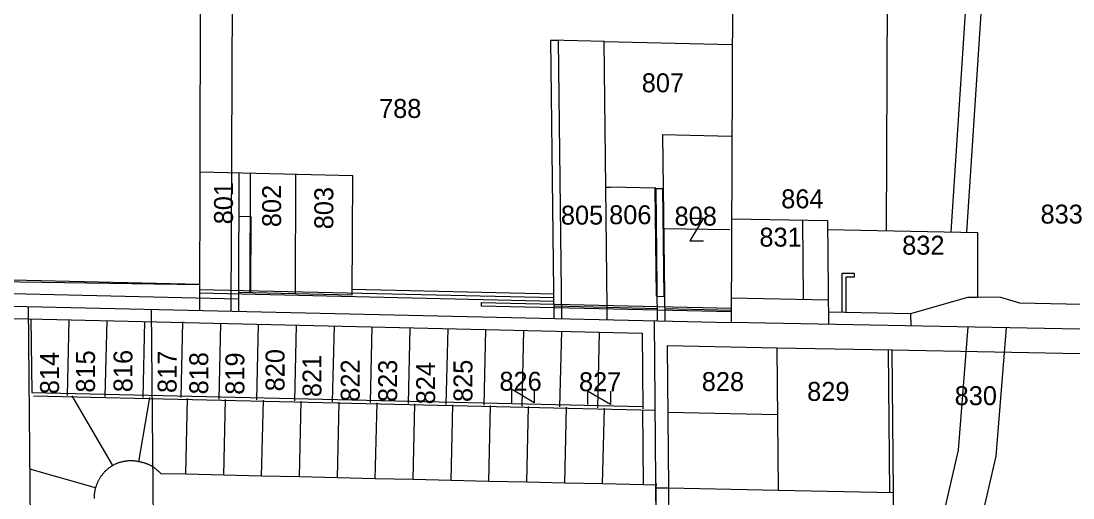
# Model space of a CAD drawing. Extents: x 582596 to 627039, y 145946 to 197316.
# Drawn here: x 613327 to 616103, y 164266 to 165524 of the extents above; entities that cross this region are included whole.
import ezdxf

# ---------------------------------------------------------------- set-up
doc = ezdxf.new("R2010")
doc.units = 0
for name, color, linetype in [('Defpoints 2', 7, 'Continuous'), ('E_RW_Easement', 7, 'Continuous'), ('E_RW_EasementUtility', 7, 'Continuous'), ('E_RW_Existing', 7, 'Continuous'), ('E_RW_SixteenthLine', 7, 'Continuous'), ('P_RW_MinorLotLine', 7, 'Continuous'), ('P_RW_PropertyConnector', 7, 'Continuous'), ('P_RW_PropertyLine', 7, 'Continuous'), ('P_RW_SectionLine', 7, 'Continuous')]:
    doc.layers.add(name, color=color, linetype=linetype)

msp = doc.modelspace()

# ---------------------------------------------------------------- linework, layer by layer
at = {"layer": 'E_RW_Easement'}
for p, q in [((615003.8, 164798), (615000.3, 165082.3)), ((615000.3, 165082.3), (615020.3, 165081.8)), ((615020.3, 165081.8), (615023.8, 164797)), ((613934.1, 165007.7), (613901.8, 165008.4)), ((613933.2, 164807.6), (613934.1, 165007.7)), ((615389.6, 164998.9), (615391.2, 164789.9)), ((613352.7, 164738), (613355.6, 164543.9)), ((613355.6, 164543.9), (614967.8, 164506.7))]:
    msp.add_line(p, q, dxfattribs=at)
at = {"layer": 'E_RW_EasementUtility'}
for p, q in [((612654.1, 164845.1), (613797.7, 164828.8)), ((613797.7, 164828.8), (612655.2, 164855.1)), ((615494.2, 164756), (615494.2, 164858.6)), ((615494.2, 164858.6), (615526.2, 164858.6)), ((615526.2, 164848.6), (615504.2, 164848.6)), ((615504.2, 164848.6), (615504.2, 164755.8)), ((615526.2, 164858.6), (615526.2, 164848.6)), ((613797.7, 164815.8), (614733.7, 164794.2)), ((614733.8, 164784.2), (613797.6, 164805.8)), ((614541.8, 164781.6), (614541.6, 164771.6)), ((615201.4, 164756.4), (614541.6, 164771.6)), ((614541.8, 164781.6), (615201.7, 164766.4)), ((615201.4, 164756.4), (615201.7, 164766.4)), ((615619.7, 164279.9), (615616.2, 164655.4))]:
    msp.add_line(p, q, dxfattribs=at)
for points in [[(615782, 164967.6), (615831.2, 165721.9), (615831, 166539.8), (616025.7, 167280.4), (615965.4, 167713.3), (615441.9, 168132.8), (615114.9, 169080.1), (615105.8, 170000.3)], [(615145.8, 169999), (615154.8, 169085.4), (615476, 168155.1), (616002.8, 167732.8), (616066.4, 167276.3), (615871, 166533), (615871.2, 165718.9), (615822.1, 164966.9)], [(615631.1, 163656.6), (615800.8, 164391.5), (615826.4, 164716.8)], [(615926.5, 164715), (615899.9, 164376.3), (615728.5, 163634.1)]]:
    msp.add_lwpolyline(points, dxfattribs=at)
at = {"layer": 'E_RW_Existing'}
for p, q in [((612606.8, 164821.2), (613901.2, 164791.4)), ((614733.9, 164772.2), (614873.9, 164769)), ((614873.9, 164769), (615005.8, 164765.9)), ((615025.7, 164765.5), (615201.3, 164761.4)), ((612560.3, 164756.2), (613346.3, 164738.1)), ((615457.5, 164756.7), (615675.7, 164752.6)), ((614969.7, 164300.1), (614967.8, 164498.2))]:
    msp.add_line(p, q, dxfattribs=at)
at = {"layer": 'E_RW_SixteenthLine'}
for p, q in [((613890.1, 167412), (613881.1, 164758.8)), ((613696.6, 162141.4), (613671.6, 164763.7))]:
    msp.add_line(p, q, dxfattribs=at)
at = {"layer": 'P_RW_MinorLotLine'}
for p, q in [((614754.3, 164738.7), (614745.6, 165472.7)), ((613902.2, 165122.8), (613901.2, 164808.4)), ((615022.5, 164976.5), (615198, 164973.9)), ((614649.4, 164508.1), (614654, 164708)), ((614849.3, 164503.5), (614853.9, 164703.4))]:
    msp.add_line(p, q, dxfattribs=at)
at = {"layer": 'P_RW_PropertyConnector'}
for p, q in [((615092.3, 165003.7), (615127.9, 165003.7)), ((615127.9, 165003.7), (615092.3, 164943.8)), ((615110.1, 164973.7), (615110.1, 164973.7)), ((615092.3, 164943.8), (615127.9, 164943.7)), ((614621.4, 164552.8), (614621.4, 164517.1)), ((614681.4, 164517.1), (614621.4, 164552.8)), ((614681.4, 164552.8), (614681.4, 164517.1)), ((614822.4, 164547.6), (614822.4, 164512)), ((614882.4, 164512), (614822.4, 164547.6)), ((614882.4, 164547.6), (614882.4, 164512)), ((614651.4, 164535), (614651.4, 164535)), ((614852.4, 164529.8), (614852.4, 164529.8))]:
    msp.add_line(p, q, dxfattribs=at)
at = {"layer": 'P_RW_PropertyLine'}
for p, q in [((613799.9, 165125.7), (613805, 167412.9)), ((615610.7, 164970.8), (615616.6, 166049.2)), ((614734.3, 164739.2), (614725.6, 165473.1)), ((614725.6, 165473.1), (614745.6, 165472.7)), ((614865.6, 165469.9), (614725.6, 165473.1)), ((614865.6, 165469.9), (615204.2, 165462.1)), ((614870.3, 165086), (614865.6, 165469.9)), ((615203.2, 165219.3), (615020.4, 165223.5)), ((615020.4, 165223.5), (615026.2, 164732.5)), ((613799.1, 164760.7), (613799.9, 165125.7)), ((613799.9, 165125.7), (614202.5, 165116.5)), ((613932.1, 165122.7), (613931.2, 164807.7)), ((614051.2, 164804.9), (614052.5, 165119.9)), ((614201.2, 164801.5), (614202.5, 165116.5)), ((614873.9, 164769), (614870.1, 165085.9)), ((614870.1, 165085.9), (614882.1, 165085.7)), ((615002.1, 165082.9), (614882.1, 165085.7)), ((615002.1, 165082.9), (615006.2, 164732.9)), ((615201.7, 165002.3), (615455.6, 164997.6)), ((615455.6, 164997.6), (615457.8, 164723.8)), ((615455.8, 164973.7), (615851.1, 164966.4)), ((615851.1, 164966.4), (615851.1, 164795.3)), ((614201.2, 164816.5), (614733.5, 164804.2)), ((613901.2, 164808.4), (613901, 164758.4)), ((613901.2, 164808.4), (614051.2, 164804.9)), ((614051.2, 164804.9), (614201.2, 164801.5)), ((615005.5, 164797.9), (615025.4, 164797.5)), ((615201.5, 164793.4), (615457.3, 164788.7)), ((615675.7, 164752.6), (615825.5, 164795.6)), ((615825.5, 164795.6), (615851.1, 164795.3)), ((615913.2, 164794.2), (615851.1, 164795.3)), ((615962.7, 164779.3), (615913.2, 164794.2)), ((613346, 164771.2), (613359.5, 163371.2)), ((614874.3, 164736), (614873.9, 164769)), ((616584.9, 164767.7), (615962.7, 164779.3)), ((613346.3, 164738.1), (614965.9, 164700.8)), ((613449.7, 164535.7), (613454.3, 164735.7)), ((613549.6, 164533.4), (613554.3, 164733.4)), ((613649.6, 164531.1), (613654.2, 164731.1)), ((613749.6, 164530.5), (613754.2, 164730.5)), ((615675.9, 164719.6), (615675.7, 164752.6)), ((613849.6, 164526.5), (613854.2, 164726.4)), ((613949.5, 164524.2), (613954.1, 164724.1)), ((614049.5, 164521.9), (614054.1, 164721.8)), ((614149.5, 164519.6), (614154.1, 164719.5)), ((614249.5, 164517.3), (614254.1, 164717.2)), ((614349.4, 164515), (614354, 164714.9)), ((614449.4, 164512.7), (614454, 164712.6)), ((614549.4, 164510.4), (614554, 164710.3)), ((614749.3, 164505.8), (614753.9, 164705.7)), ((614965.9, 164700.8), (614967.9, 164500.7)), ((615032.2, 164667.3), (615035.8, 164292.4)), ((615322, 164661.2), (615325.6, 164286.3)), ((615626.1, 164655.5), (615322, 164661.2)), ((616528.5, 164638.8), (615625.8, 164655.5)), ((616528.5, 164638.8), (615626.1, 164655.5)), ((615629.7, 164279.9), (615626.1, 164655.5)), ((613360.3, 164535.2), (615000.8, 164497.5)), ((613569.4, 164351.6), (613461.8, 164535.1)), ((613637.7, 164361.5), (613666.7, 164530.4)), ((613762.2, 164328.1), (613766.7, 164528)), ((613862.1, 164325.8), (613866.7, 164525.7)), ((613962.1, 164323.5), (613966.7, 164523.4)), ((614062.1, 164321.1), (614066.6, 164521.1)), ((614162.1, 164318.8), (614166.6, 164518.8)), ((614262.1, 164316.5), (614266.6, 164516.5)), ((614362, 164314.2), (614366.6, 164514.1)), ((614462, 164311.9), (614466.6, 164511.8)), ((614562, 164309.5), (614566.5, 164509.5)), ((614662, 164307.2), (614666.5, 164507.2)), ((614761.9, 164304.9), (614766.5, 164505.4)), ((614861.9, 164302.6), (614866.5, 164502.6)), ((615033.9, 164492.4), (615323.7, 164486.3)), ((613523.7, 164292.7), (613350.1, 164342.1)), ((613555.4, 164341.8), (613554.2, 164340.7)), ((613556.7, 164342.9), (613555.4, 164341.8)), ((613558.2, 164344), (613556.7, 164342.9)), ((613559.5, 164345.1), (613558.2, 164344)), ((613561.1, 164346.1), (613559.5, 164345.1)), ((613562.3, 164347.2), (613561.1, 164346.1)), ((613563.9, 164348.1), (613562.3, 164347.2)), ((613565.4, 164349.1), (613563.9, 164348.1)), ((613566.7, 164350), (613565.4, 164349.1)), ((613569.4, 164351.6), (613566.7, 164350)), ((613571, 164352.5), (613569.4, 164351.6)), ((613572.5, 164353.2), (613571, 164352.5)), ((613574, 164354), (613572.5, 164353.2)), ((613575.5, 164354.7), (613574, 164354)), ((613577.3, 164355.4), (613575.5, 164354.7)), ((613578.8, 164356.1), (613577.3, 164355.4)), ((613580.6, 164356.8), (613578.8, 164356.1)), ((613582.1, 164357.4), (613580.6, 164356.8)), ((613583.6, 164358), (613582.1, 164357.4)), ((613585.4, 164358.6), (613583.6, 164358)), ((613587.1, 164359.1), (613585.4, 164358.6)), ((613588.7, 164359.6), (613587.1, 164359.1)), ((613590.4, 164360.1), (613588.7, 164359.6)), ((613592.2, 164360.5), (613590.4, 164360.1)), ((613593.7, 164360.9), (613592.2, 164360.5)), ((613595.4, 164361.3), (613593.7, 164360.9)), ((613597.2, 164361.7), (613595.4, 164361.3)), ((613599, 164362), (613597.2, 164361.7)), ((613600.7, 164362.3), (613599, 164362)), ((613602.2, 164362.6), (613600.7, 164362.3)), ((613604, 164362.8), (613602.2, 164362.6)), ((613605.7, 164363), (613604, 164362.8)), ((613607.5, 164363.2), (613605.7, 164363)), ((613609.3, 164363.4), (613607.5, 164363.2)), ((613611, 164363.5), (613609.3, 164363.4)), ((613612.8, 164363.6), (613611, 164363.5)), ((613614.5, 164363.6), (613612.8, 164363.6)), ((613616.3, 164363.7), (613614.5, 164363.6)), ((613618, 164363.6), (613616.3, 164363.7)), ((613619.8, 164363.6), (613618, 164363.6)), ((613621.5, 164363.5), (613619.8, 164363.6)), ((613623.3, 164363.4), (613621.5, 164363.5)), ((613625, 164363.3), (613623.3, 164363.4)), ((613626.8, 164363.2), (613625, 164363.3)), ((613628.5, 164363), (613626.8, 164363.2)), ((613630.2, 164362.8), (613628.5, 164363)), ((613632, 164362.5), (613630.2, 164362.8)), ((613633.7, 164362.2), (613632, 164362.5)), ((613635.2, 164361.9), (613633.7, 164362.2)), ((613637.7, 164361.5), (613635.2, 164361.9)), ((613639.5, 164361.2), (613637.7, 164361.5)), ((613641.2, 164360.9), (613639.5, 164361.2)), ((613642.9, 164360.5), (613641.2, 164360.9)), ((613644.7, 164360.1), (613642.9, 164360.5)), ((613646.2, 164359.7), (613644.7, 164360.1)), ((613647.9, 164359.3), (613646.2, 164359.7)), ((613649.7, 164358.8), (613647.9, 164359.3)), ((613651.4, 164358.3), (613649.7, 164358.8)), ((613652.9, 164357.8), (613651.4, 164358.3)), ((613654.6, 164357.3), (613652.9, 164357.8)), ((613656.4, 164356.7), (613654.6, 164357.3)), ((613657.8, 164356.1), (613656.4, 164356.7)), ((613659.6, 164355.5), (613657.8, 164356.1)), ((613661.3, 164354.8), (613659.6, 164355.5)), ((613662.8, 164354.1), (613661.3, 164354.8)), ((613664.3, 164353.4), (613662.8, 164354.1)), ((613666, 164352.6), (613664.3, 164353.4)), ((613667.5, 164351.9), (613666, 164352.6)), ((613669, 164351.1), (613667.5, 164351.9)), ((613670.7, 164350.2), (613669, 164351.1)), ((613672.2, 164349.4), (613670.7, 164350.2)), ((613673.6, 164348.5), (613672.2, 164349.4)), ((613675.1, 164347.6), (613673.6, 164348.5)), ((613676.6, 164346.6), (613675.1, 164347.6)), ((613678.1, 164345.7), (613676.6, 164346.6)), ((613679.6, 164344.7), (613678.1, 164345.7)), ((613681, 164343.7), (613679.6, 164344.7)), ((613682.3, 164342.6), (613681, 164343.7)), ((613683.7, 164341.6), (613682.3, 164342.6)), ((613685, 164340.5), (613683.7, 164341.6)), ((613533.3, 164315.2), (613532.5, 164313.6)), ((613534, 164316.7), (613533.3, 164315.2)), ((613535.1, 164318.2), (613534, 164316.7)), ((613535.9, 164319.6), (613535.1, 164318.2)), ((613536.9, 164321.1), (613535.9, 164319.6)), ((613537.9, 164322.5), (613536.9, 164321.1)), ((613539, 164324), (613537.9, 164322.5)), ((613540, 164325.4), (613539, 164324)), ((613541.1, 164326.7), (613540, 164325.4)), ((613542.1, 164328.1), (613541.1, 164326.7)), ((613543.1, 164329.5), (613542.1, 164328.1)), ((613544.4, 164330.8), (613543.1, 164329.5)), ((613545.4, 164332.1), (613544.4, 164330.8)), ((613546.7, 164333.4), (613545.4, 164332.1)), ((613547.8, 164334.7), (613546.7, 164333.4)), ((613549, 164335.9), (613547.8, 164334.7)), ((613550.3, 164337.1), (613549, 164335.9)), ((613551.6, 164338.3), (613550.3, 164337.1)), ((613552.9, 164339.5), (613551.6, 164338.3)), ((613554.2, 164340.7), (613552.9, 164339.5)), ((613686.4, 164339.4), (613685, 164340.5)), ((613687.6, 164338.3), (613686.4, 164339.4)), ((613689.1, 164337.1), (613687.6, 164338.3)), ((613690.3, 164335.9), (613689.1, 164337.1)), ((613691.6, 164334.7), (613690.3, 164335.9)), ((613692.8, 164333.5), (613691.6, 164334.7)), ((613694, 164332.3), (613692.8, 164333.5)), ((613695.2, 164331), (613694, 164332.3)), ((613696.7, 164329.6), (613695.2, 164331)), ((613762.2, 164328.1), (613696.7, 164329.6)), ((613862.1, 164325.8), (613762.2, 164328.1)), ((613962.1, 164323.5), (613862.1, 164325.8)), ((614062.1, 164321.1), (613962.1, 164323.5)), ((614162.1, 164318.8), (614062.1, 164321.1)), ((614262.1, 164316.5), (614162.1, 164318.8)), ((614362, 164314.2), (614262.1, 164316.5)), ((614462, 164311.9), (614362, 164314.2)), ((613522.3, 164286.9), (613522, 164285.2)), ((613522.6, 164288.7), (613522.3, 164286.9)), ((613523.1, 164290.3), (613522.6, 164288.7)), ((613523.7, 164292.7), (613523.1, 164290.3)), ((613524.2, 164294.4), (613523.7, 164292.7)), ((613524.8, 164296.1), (613524.2, 164294.4)), ((613525.3, 164297.7), (613524.8, 164296.1)), ((613525.9, 164299.4), (613525.3, 164297.7)), ((613526.4, 164301), (613525.9, 164299.4)), ((613527.2, 164302.6), (613526.4, 164301)), ((613527.7, 164304.2), (613527.2, 164302.6)), ((613528.5, 164305.8), (613527.7, 164304.2)), ((613529.3, 164307.4), (613528.5, 164305.8)), ((613529.9, 164309), (613529.3, 164307.4)), ((613530.6, 164310.6), (613529.9, 164309)), ((613531.4, 164312.1), (613530.6, 164310.6)), ((613532.5, 164313.6), (613531.4, 164312.1)), ((614562, 164309.5), (614462, 164311.9)), ((614662, 164307.2), (614562, 164309.5)), ((614761.9, 164304.9), (614662, 164307.2)), ((614861.9, 164302.6), (614761.9, 164304.9)), ((614969.9, 164300.1), (614861.9, 164302.6)), ((615003.1, 164299.3), (614969.9, 164300.1)), ((615003, 164303.9), (615003, 164303)), ((615003, 164303), (615003, 164303.9)), ((615003, 164303), (615003.1, 164299.3)), ((615003.1, 164299.3), (615003, 164303)), ((615003, 164292.5), (615003.1, 164299.3)), ((615036.2, 164291.8), (615003, 164292.5)), ((615004.7, 164125.3), (615003, 164292.5)), ((615003, 164292.5), (615036.2, 164291.8)), ((615035.8, 164292.4), (615037.7, 164089.5)), ((615035.8, 164292.4), (615325.6, 164286.3)), ((615325.6, 164286.3), (615629.7, 164279.9)), ((613520.1, 164267.9), (613520, 164266.2)), ((613520, 164266.2), (613520, 164264.4)), ((613520.2, 164273.1), (613520.1, 164271.4)), ((613520.1, 164271.4), (613520.1, 164269.7)), ((613520.1, 164269.7), (613520.1, 164267.9)), ((613520.5, 164274.9), (613520.2, 164273.1)), ((613520.8, 164278.3), (613520.5, 164276.6)), ((613520.5, 164276.6), (613520.5, 164274.9)), ((613521.1, 164280.1), (613520.8, 164278.3)), ((613521.2, 164281.8), (613521.1, 164280.1)), ((613521.7, 164283.5), (613521.2, 164281.8)), ((613522, 164285.2), (613521.7, 164283.5)), ((615631.6, 164077.6), (615629.7, 164279.9))]:
    msp.add_line(p, q, dxfattribs=at)
msp.add_lwpolyline([(615322, 164661.2), (615199.8, 164663.4), (615032.2, 164667.3)], dxfattribs=at)
at = {"layer": 'P_RW_SectionLine'}
for p, q in [((615212.2, 167389), (615201.2, 164728.4)), ((612561.1, 164789.2), (615201.2, 164728.4)), ((615023.3, 162125.7), (614998.6, 164733.1)), ((617840.9, 164679.4), (615201.2, 164728.4))]:
    msp.add_line(p, q, dxfattribs=at)

# ---------------------------------------------------------------- texts
at = {"layer": 'Defpoints 2'}
for s, p in [('807', (614965.2, 165336)), ('788', (614272, 165268.3)), ('864', (615333.3, 165029.9)), ('805', (614751.9, 164986.9)), ('806', (614879.2, 164987.9)), ('833', (616017.7, 164989.6)), ('808', (615051.8, 164984.2)), ('831', (615275.7, 164928.8)), ('832', (615652.6, 164907.6)), ('826', (614589.6, 164548.6)), ('827', (614799.6, 164547.4)), ('828', (615123.7, 164547.8)), ('829', (615401.8, 164521.9)), ('830', (615791, 164510.6))]:
    msp.add_text(s, height=50, dxfattribs=at).set_placement(p)
for s, p in [('801', (613886.5, 164987.7)), ('802', (614013.4, 164980.2)), ('803', (614151.2, 164974.6)), ('814', (613427.4, 164539.6)), ('815', (613522.3, 164543.6)), ('816', (613621.2, 164544.9)), ('817', (613737.7, 164542.7)), ('818', (613821.2, 164539)), ('820', (614022.5, 164547)), ('819', (613916.5, 164538.1)), ('821', (614119.8, 164531.8)), ('822', (614220.9, 164519.6)), ('823', (614319.7, 164518.9)), ('824', (614419.9, 164512.8)), ('825', (614518.4, 164518.9))]:
    msp.add_text(s, height=50, rotation=90, dxfattribs=at).set_placement(p)

doc.saveas('drawing.dxf')
